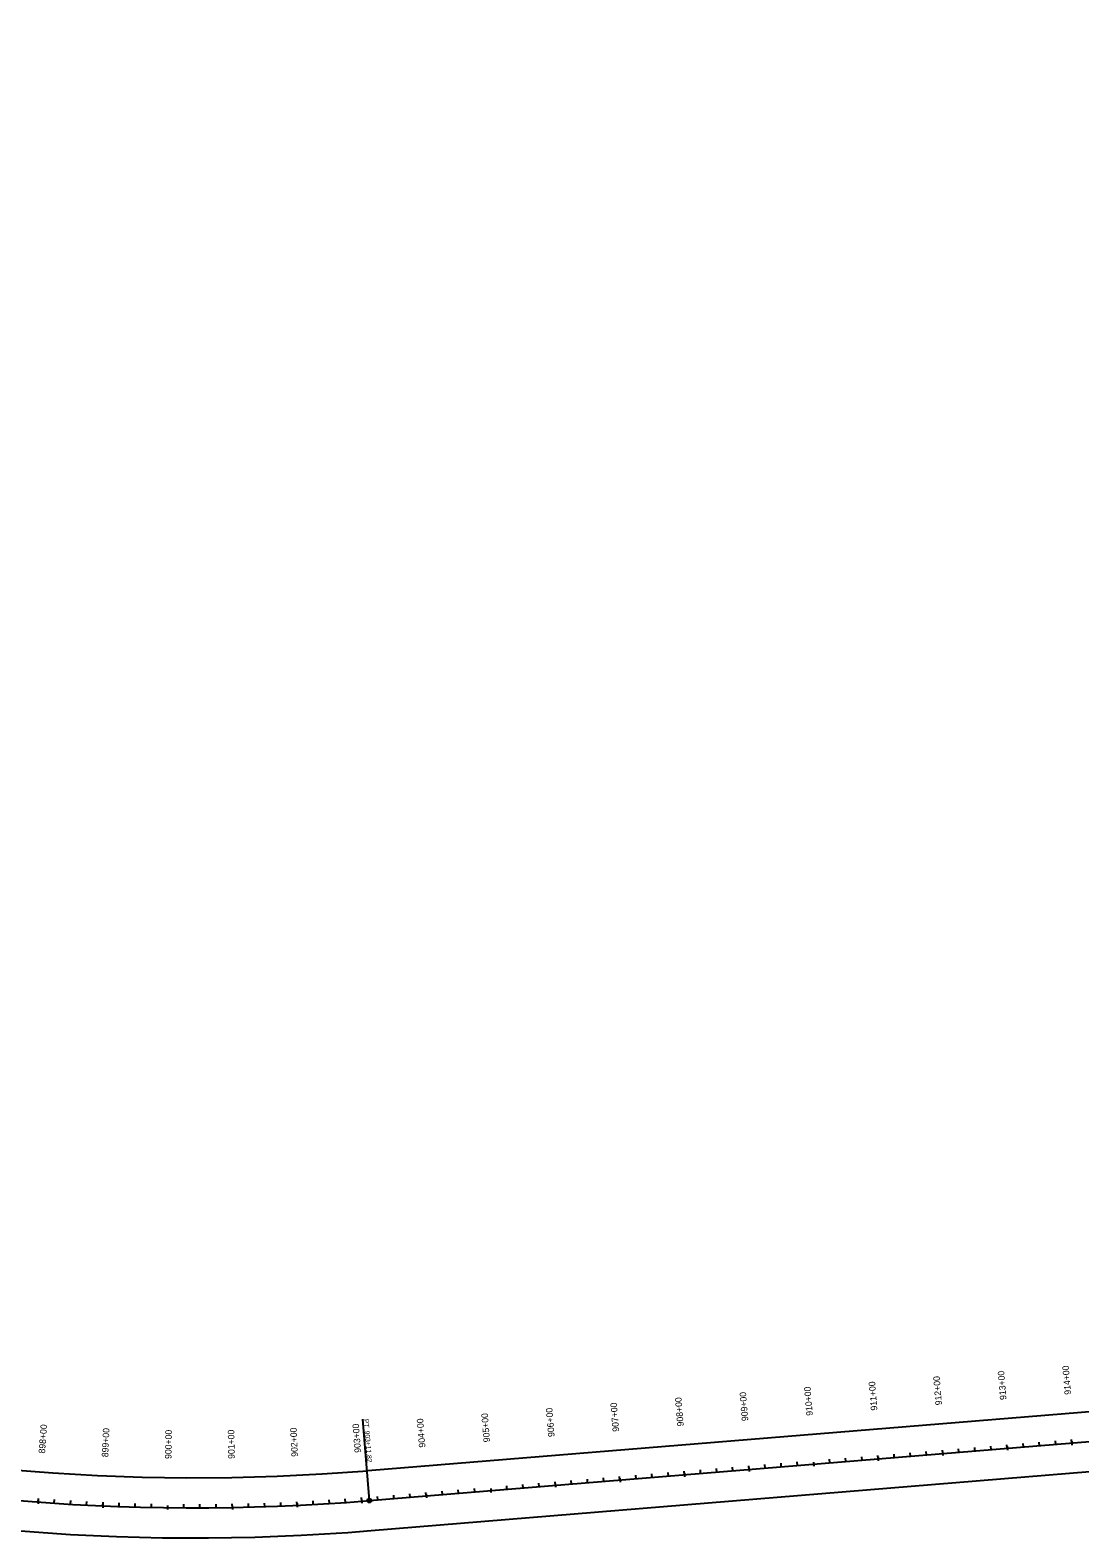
# Model space of a CAD drawing. Extents: x 14448949 to 14455476, y 8570587 to 8573998.
# Drawn here: x 14452210 to 14453831, y 8570851 to 8573181 of the extents above; entities that cross this region are included whole.
import ezdxf

# ---------------------------------------------------------------- set-up
doc = ezdxf.new("R2010")
doc.units = 0
for name, color, linetype in [('Alignment', 7, 'Continuous'), ('TextAlignment', 7, 'Continuous'), ('TextAlignmentLrg', 7, 'Continuous'), ('TextAlignmentSml', 7, 'Continuous'), ('TextNonPlot', 7, 'Continuous')]:
    doc.layers.add(name, color=color, linetype=linetype)

msp = doc.modelspace()

# ---------------------------------------------------------------- linework, layer by layer
at = {"layer": 'Alignment'}
msp.add_line((14452734, 8570908.9), (14454506.7, 8571054.2), dxfattribs=at)
msp.add_line((14452734, 8570908.9), (14454506.7, 8571054.2), dxfattribs=at)
msp.add_arc((14452465.5, 8574183.5), 3285.7, 198.0445, 274.688, dxfattribs=at)
msp.add_arc((14452465.5, 8574183.5), 3285.7, 198.0445, 274.688, dxfattribs=at)
at = {"layer": 'TextAlignment'}
for p in [(14452734, 8570908.9), (14452723.7, 8571034.4)]:
    msp.add_line(p, (14452723.7, 8571034.4), dxfattribs=at)
msp.add_circle((14452734, 8570908.9), 3.12, dxfattribs=at)
at = {"layer": 'TextAlignmentLrg'}
for p, q in [((14453818.5, 8570997.8), (14453818.1, 8571003.2)), ((14453519.5, 8570973.3), (14453519.1, 8570978.7)), ((14453619.2, 8570981.4), (14453618.8, 8570986.9)), ((14453718.9, 8570989.6), (14453718.4, 8570995.1)), ((14453220.5, 8570948.8), (14453220.1, 8570954.2)), ((14453320.2, 8570956.9), (14453319.8, 8570962.4)), ((14453419.6, 8570968.1), (14453420.1, 8570962)), ((14452921.3, 8570927.3), (14452921.8, 8570921.2)), ((14453021.2, 8570932.4), (14453020.8, 8570937.8)), ((14453120.9, 8570940.6), (14453120.4, 8570946)), ((14452222.7, 8570906.8), (14452223.1, 8570912.3)), ((14452322.5, 8570901), (14452322.8, 8570906.4)), ((14452522.5, 8570898.4), (14452522.4, 8570903.8)), ((14452622.4, 8570901.6), (14452622.2, 8570907.1)), ((14452722.2, 8570907.9), (14452721.8, 8570913.4)), ((14452821.9, 8570916.1), (14452821.4, 8570921.5)), ((14452422.5, 8570901.2), (14452422.4, 8570895.1))]:
    msp.add_line(p, q, dxfattribs=at)
at = {"layer": 'TextAlignmentSml'}
for p, q in [((14453743.8, 8570991.7), (14453743.3, 8570997.1)), ((14453768.7, 8570993.7), (14453768.3, 8570999.1)), ((14453793.6, 8570995.7), (14453793.2, 8571001.2)), ((14453818.3, 8571000.8), (14453818.8, 8570994.7)), ((14453444.8, 8570967.1), (14453444.3, 8570972.6)), ((14453469.7, 8570969.2), (14453469.3, 8570974.6)), ((14453494.6, 8570971.2), (14453494.2, 8570976.7)), ((14453519.3, 8570976.3), (14453519.8, 8570970.2)), ((14453544.5, 8570975.3), (14453544, 8570980.8)), ((14453569.4, 8570977.4), (14453568.9, 8570982.8)), ((14453594.3, 8570979.4), (14453593.8, 8570984.8)), ((14453619, 8570984.5), (14453619.5, 8570978.4)), ((14453644.1, 8570983.5), (14453643.7, 8570988.9)), ((14453669, 8570985.5), (14453668.6, 8570991)), ((14453694, 8570987.6), (14453693.5, 8570993)), ((14453718.6, 8570992.7), (14453719.1, 8570986.6)), ((14453170.7, 8570944.7), (14453170.3, 8570950.1)), ((14453195.6, 8570946.7), (14453195.2, 8570952.1)), ((14453220.3, 8570951.8), (14453220.8, 8570945.7)), ((14453245.5, 8570950.8), (14453245, 8570956.2)), ((14453270.4, 8570952.8), (14453269.9, 8570958.3)), ((14453295.3, 8570954.9), (14453294.8, 8570960.3)), ((14453320, 8570960), (14453320.5, 8570953.9)), ((14453345.1, 8570959), (14453344.7, 8570964.4)), ((14453370, 8570961), (14453369.6, 8570966.5)), ((14453395, 8570963.1), (14453394.5, 8570968.5)), ((14453419.6, 8570968.1), (14453420.1, 8570962)), ((14452871.7, 8570920.1), (14452871.3, 8570925.6)), ((14452896.6, 8570922.2), (14452896.2, 8570927.6)), ((14452921.3, 8570927.3), (14452921.8, 8570921.2)), ((14452946.5, 8570926.3), (14452946, 8570931.7)), ((14452971.4, 8570928.3), (14452970.9, 8570933.8)), ((14452996.3, 8570930.4), (14452995.8, 8570935.8)), ((14453021, 8570935.5), (14453021.5, 8570929.4)), ((14453046.1, 8570934.4), (14453045.7, 8570939.9)), ((14453071, 8570936.5), (14453070.6, 8570941.9)), ((14453096, 8570938.5), (14453095.5, 8570944)), ((14453120.6, 8570943.6), (14453121.1, 8570937.5)), ((14453145.8, 8570942.6), (14453145.3, 8570948.1)), ((14452222.9, 8570909.9), (14452222.5, 8570903.8)), ((14452247.6, 8570905.1), (14452248, 8570910.5)), ((14452272.6, 8570903.5), (14452272.9, 8570909)), ((14452297.5, 8570902.2), (14452297.8, 8570907.6)), ((14452322.7, 8570904), (14452322.4, 8570897.9)), ((14452347.5, 8570900), (14452347.7, 8570905.4)), ((14452372.5, 8570899.2), (14452372.6, 8570904.6)), ((14452397.5, 8570898.6), (14452397.6, 8570904)), ((14452447.5, 8570897.9), (14452447.5, 8570903.4)), ((14452472.5, 8570897.9), (14452472.5, 8570903.3)), ((14452497.5, 8570898), (14452497.4, 8570903.5)), ((14452547.5, 8570898.9), (14452547.3, 8570904.3)), ((14452572.5, 8570899.6), (14452572.3, 8570905.1)), ((14452597.4, 8570900.5), (14452597.2, 8570906)), ((14452622.3, 8570904.7), (14452622.6, 8570898.6)), ((14452647.4, 8570902.9), (14452647.1, 8570908.4)), ((14452672.3, 8570904.4), (14452672, 8570909.8)), ((14452697.3, 8570906), (14452696.9, 8570911.5)), ((14452722, 8570911), (14452722.5, 8570904.9)), ((14452747.1, 8570909.9), (14452746.7, 8570915.4)), ((14452772, 8570912), (14452771.6, 8570917.4)), ((14452797, 8570914), (14452796.5, 8570919.5)), ((14452821.6, 8570919.1), (14452822.1, 8570913)), ((14452846.8, 8570918.1), (14452846.3, 8570923.5)), ((14452422.5, 8570901.2), (14452422.4, 8570895.1)), ((14452522.4, 8570901.4), (14452522.5, 8570895.3))]:
    msp.add_line(p, q, dxfattribs=at)
at = {"layer": 'TextNonPlot'}
for p, q in [((14452731.4, 8570955.1), (14454502.9, 8571100.3)), ((14452736.6, 8570862.5), (14454513.1, 8571008.3))]:
    msp.add_line(p, q, dxfattribs=at)
for centre, radius, start, end in [((14452466.6, 8574184.2), 3240, 198.0445, 274.688), ((14452464.1, 8574181.3), 3330, 198.0899, 274.6933)]:
    msp.add_arc(centre, radius, start, end, dxfattribs=at)

# ---------------------------------------------------------------- texts
at = {"layer": 'TextAlignment'}
for s, p in [('PT', (14452725.3, 8571034.6)), ('903+11.82', (14452726.8, 8571016.5))]:
    msp.add_text(s, height=7.5, rotation=274.688, dxfattribs=at).set_placement(p)
at = {"layer": 'TextAlignmentLrg'}
for s, rotation, p in [('910+00', 94.688, (14453418.7, 8571040.3)), ('905+00', 94.688, (14452920.4, 8570999.4)), ('900+00', 89.2505, (14452428.5, 8570973.1))]:
    msp.add_text(s, height=10.02, rotation=rotation, dxfattribs=at).set_placement(p)
at = {"layer": 'TextAlignmentSml'}
for s, rotation, p in [('914+00', 94.688, (14453817.4, 8571072.9)), ('911+00', 94.688, (14453518.4, 8571048.4)), ('912+00', 94.688, (14453618.1, 8571056.6)), ('913+00', 94.688, (14453717.7, 8571064.8)), ('908+00', 94.688, (14453219.4, 8571023.9)), ('909+00', 94.688, (14453319.1, 8571032.1)), ('910+00', 94.688, (14453418.7, 8571040.3)), ('905+00', 94.688, (14452920.4, 8570999.4)), ('906+00', 94.688, (14453020.1, 8571007.6)), ('907+00', 94.688, (14453119.7, 8571015.7)), ('898+00', 85.7629, (14452233.2, 8570981.3)), ('899+00', 87.5067, (14452330.8, 8570975.7)), ('902+00', 92.7381, (14452623.8, 8570976.8)), ('903+00', 94.4819, (14452721.3, 8570983.1)), ('904+00', 94.688, (14452820.7, 8570991.2)), ('900+00', 89.2505, (14452428.5, 8570973.1)), ('901+00', 90.9943, (14452526.2, 8570973.4))]:
    msp.add_text(s, height=10.02, rotation=rotation, dxfattribs=at).set_placement(p)

doc.saveas('drawing.dxf')
